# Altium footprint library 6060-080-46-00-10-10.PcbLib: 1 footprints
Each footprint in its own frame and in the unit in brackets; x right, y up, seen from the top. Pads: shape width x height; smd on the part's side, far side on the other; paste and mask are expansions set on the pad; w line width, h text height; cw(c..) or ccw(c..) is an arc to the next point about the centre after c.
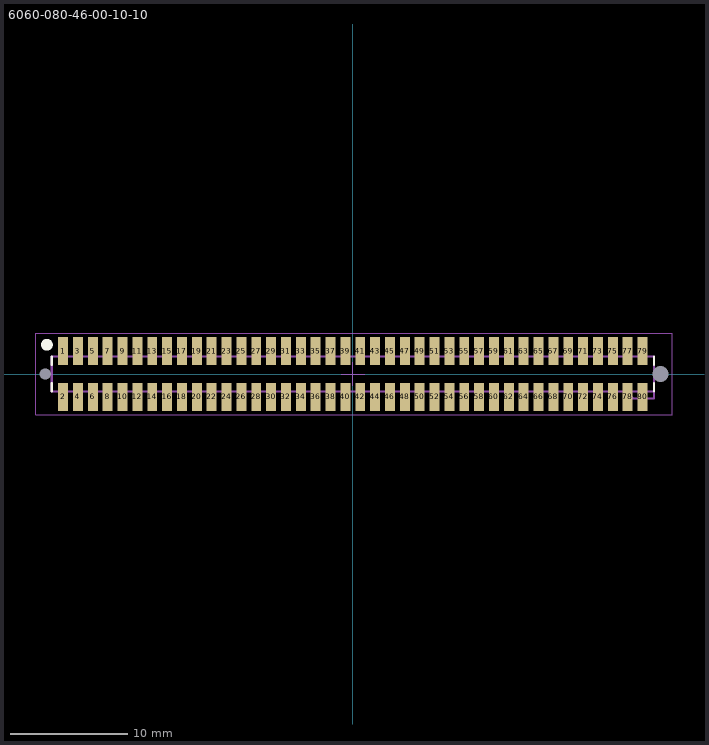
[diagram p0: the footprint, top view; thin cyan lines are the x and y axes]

## 6060-080-46-00-10-10 [mm]
height 4.5
pads (82):
  rect 0.85x2.4 smd: 1(-24.765,1.95) 2(-24.765,-1.95) 3(-23.495,1.95) 4(-23.495,-1.95) 5(-22.225,1.95) 6(-22.225,-1.95) 7(-20.955,1.95) 8(-20.955,-1.95) 9(-19.685,1.95) 10(-19.685,-1.95) 11(-18.415,1.95) 12(-18.415,-1.95) 13(-17.145,1.95) 14(-17.145,-1.95) 15(-15.875,1.95) 16(-15.875,-1.95) 17(-14.605,1.95) 18(-14.605,-1.95) 19(-13.335,1.95) 20(-13.335,-1.95) 21(-12.065,1.95) 22(-12.065,-1.95) 23(-10.795,1.95) 24(-10.795,-1.95) 25(-9.525,1.95) 26(-9.525,-1.95) 27(-8.255,1.95) 28(-8.255,-1.95) 29(-6.985,1.95) 30(-6.985,-1.95) 31(-5.715,1.95) 32(-5.715,-1.95) 33(-4.445,1.95) 34(-4.445,-1.95) 35(-3.175,1.95) 36(-3.175,-1.95) 37(-1.905,1.95) 38(-1.905,-1.95) 39(-0.635,1.95) 40(-0.635,-1.95) 41(0.635,1.95) 42(0.635,-1.95) 43(1.905,1.95) 44(1.905,-1.95) 45(3.175,1.95) 46(3.175,-1.95) 47(4.445,1.95) 48(4.445,-1.95) 49(5.715,1.95) 50(5.715,-1.95) 51(6.985,1.95) 52(6.985,-1.95) 53(8.255,1.95) 54(8.255,-1.95) 55(9.525,1.95) 56(9.525,-1.95) 57(10.795,1.95) 58(10.795,-1.95) 59(12.065,1.95) 60(12.065,-1.95) 61(13.335,1.95) 62(13.335,-1.95) 63(14.605,1.95) 64(14.605,-1.95) 65(15.875,1.95) 66(15.875,-1.95) 67(17.145,1.95) 68(17.145,-1.95) 69(18.415,1.95) 70(18.415,-1.95) 71(19.685,1.95) 72(19.685,-1.95) 73(20.955,1.95) 74(20.955,-1.95) 75(22.225,1.95) 76(22.225,-1.95) 77(23.495,1.95) 78(23.495,-1.95) 79(24.765,1.95) 80(24.765,-1.95)
  round 0 hole 0.95 unplated: H1(-26.29,0)
  round 0 hole 1.35 unplated: H2(26.29,0)
Top Overlay:
  circle w0.5: c-26.15,2.5 r0.25
  lines w0.2: -25.75,-1.5 -25.75,-0.8 ; -25.75,0.8 -25.75,1.5 ; 25.75,-1.5 25.75,-0.8 ; 25.75,0.8 25.75,1.5
Assembly Top:
  lines w0.2: 23.35,-1.5 23.95,-2.1 ; 23.95,-2.1 25.75,-2.1 25.75,-1.5 ; 23.95,-2.1 23.95,-2.1 ; 25.75,-1.5 -25.75,-1.5 -25.75,1.5 25.75,1.5 25.75,-1.5
  text "80" at 23.75,-1.25 h1
  text "79" at 23.75,0.25 h1
  text "1" at -24.9,0.25 h1
  text "2" at -25.15,-1.25 h1
  text ".Designator" at -2,-0.5 h1
Courtyard Top:
  lines w0.05: -1,0 1,0 ; 0,-1 0,1 ; -27.1,-3.5 -27.1,3.5 27.3,3.5 27.3,-3.5 -27.1,-3.5
3D body: height 4.5, standoff 0, extent -25.75,-1.5 25.75,1.5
